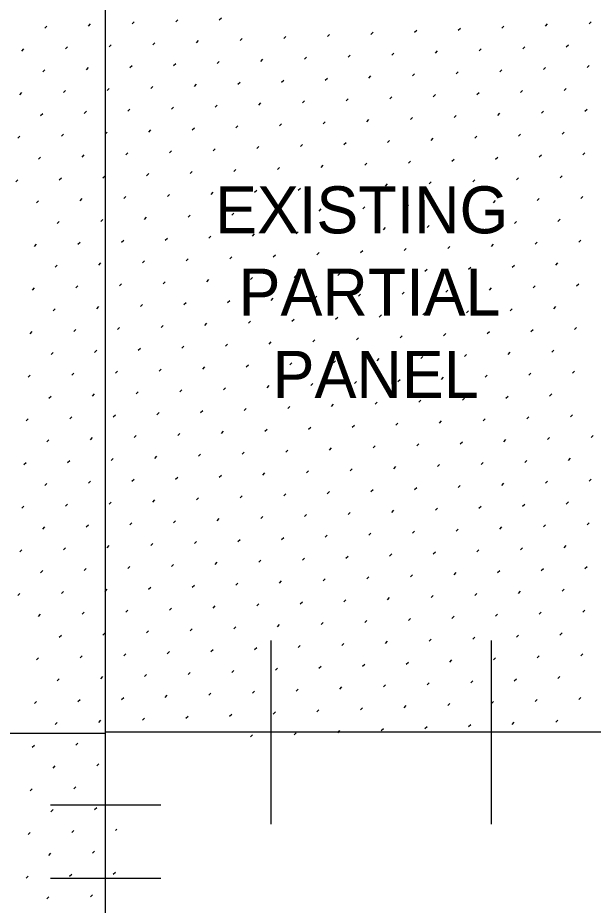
# Model space of a CAD drawing. Extents: x 49991.4 to 50021, y 49987.6 to 50011.4.
# Drawn here: x 50009.66 to 50010.64, y 49995.997 to 49997.507 of the extents above; entities that cross this region are included whole.
import ezdxf

# ---------------------------------------------------------------- set-up
doc = ezdxf.new("R2010")
doc.units = 0
for name, color, linetype in [('Level 1', 7, 'Continuous'), ('Level 10', 7, 'Continuous'), ('Level 2', 7, 'Continuous'), ('Level 4', 7, 'Continuous')]:
    doc.layers.add(name, color=color, linetype=linetype)

msp = doc.modelspace()

# ---------------------------------------------------------------- linework, layer by layer
at = {"layer": 'Level 1'}
for p, q in [((50009.8098, 49996.2901), (50009.8098, 49997.7903)), ((50008.8723, 49996.2901), (50009.8098, 49996.2901)), ((50011.6848, 49996.2915), (50009.8098, 49996.2915)), ((50009.8098, 49994.7903), (50009.8098, 49996.2901))]:
    msp.add_line(p, q, dxfattribs=at)
at = {"layer": 'Level 10'}
for p, q in [((50009.8548, 49997.4965), (50009.8584, 49997.5)), ((50009.9291, 49997.5), (50009.9326, 49997.5036)), ((50010.0033, 49997.5036), (50010.0069, 49997.5071)), ((50010.6327, 49997.4966), (50010.6362, 49997.5001)), ((50009.7063, 49997.4894), (50009.7098, 49997.4929)), ((50009.7806, 49997.4929), (50009.7841, 49997.4965)), ((50010.2614, 49997.4788), (50010.265, 49997.4824)), ((50010.3357, 49997.4824), (50010.3392, 49997.4859)), ((50010.4099, 49997.4859), (50010.4135, 49997.4895)), ((50010.4842, 49997.4895), (50010.4877, 49997.493)), ((50010.5585, 49997.493), (50010.562, 49997.4965)), ((50009.9644, 49997.4647), (50009.968, 49997.4682)), ((50010.0387, 49997.4682), (50010.0422, 49997.4717)), ((50010.1129, 49997.4718), (50010.1165, 49997.4753)), ((50010.1872, 49997.4753), (50010.1907, 49997.4788)), ((50009.6674, 49997.4505), (50009.6709, 49997.454)), ((50009.7417, 49997.454), (50009.7452, 49997.4576)), ((50009.8159, 49997.4576), (50009.8195, 49997.4611)), ((50009.8902, 49997.4611), (50009.8937, 49997.4647)), ((50010.4453, 49997.4506), (50010.4488, 49997.4541)), ((50010.5196, 49997.4541), (50010.5231, 49997.4576)), ((50010.5938, 49997.4577), (50010.5973, 49997.4612)), ((50010.1483, 49997.4364), (50010.1518, 49997.4399)), ((50010.2225, 49997.4399), (50010.2261, 49997.4435)), ((50010.2968, 49997.4435), (50010.3003, 49997.447)), ((50010.371, 49997.447), (50010.3746, 49997.4506)), ((50009.777, 49997.4187), (50009.7806, 49997.4222)), ((50009.8513, 49997.4222), (50009.8548, 49997.4258)), ((50009.9255, 49997.4258), (50009.9291, 49997.4293)), ((50009.9998, 49997.4293), (50010.0033, 49997.4328)), ((50010.074, 49997.4329), (50010.0776, 49997.4364)), ((50010.5549, 49997.4188), (50010.5584, 49997.4223)), ((50010.6292, 49997.4223), (50010.6327, 49997.4258)), ((50009.7028, 49997.4151), (50009.7063, 49997.4187)), ((50010.2579, 49997.4046), (50010.2614, 49997.4081)), ((50010.3321, 49997.4081), (50010.3357, 49997.4117)), ((50010.4064, 49997.4117), (50010.4099, 49997.4152)), ((50010.4807, 49997.4152), (50010.4842, 49997.4187)), ((50009.9609, 49997.3904), (50009.9644, 49997.394)), ((50010.0351, 49997.394), (50010.0387, 49997.3975)), ((50010.1094, 49997.3975), (50010.1129, 49997.401)), ((50010.1836, 49997.401), (50010.1872, 49997.4046)), ((50009.6639, 49997.3762), (50009.6674, 49997.3798)), ((50009.7381, 49997.3798), (50009.7417, 49997.3833)), ((50009.8124, 49997.3833), (50009.8159, 49997.3869)), ((50009.8866, 49997.3869), (50009.8902, 49997.3904)), ((50010.4418, 49997.3763), (50010.4453, 49997.3799)), ((50010.516, 49997.3799), (50010.5195, 49997.3834)), ((50010.5903, 49997.3834), (50010.5938, 49997.3869)), ((50010.0705, 49997.3586), (50010.074, 49997.3621)), ((50010.1447, 49997.3621), (50010.1483, 49997.3657)), ((50010.219, 49997.3657), (50010.2225, 49997.3692)), ((50010.2933, 49997.3692), (50010.2968, 49997.3728)), ((50010.3675, 49997.3728), (50010.371, 49997.3763)), ((50009.7735, 49997.3444), (50009.777, 49997.348)), ((50009.8477, 49997.348), (50009.8513, 49997.3515)), ((50009.922, 49997.3515), (50009.9255, 49997.3551)), ((50009.9962, 49997.3551), (50009.9998, 49997.3586)), ((50010.5514, 49997.3445), (50010.5549, 49997.348)), ((50010.6256, 49997.348), (50010.6292, 49997.3516)), ((50009.6992, 49997.3409), (50009.7028, 49997.3444)), ((50010.2544, 49997.3303), (50010.2579, 49997.3339)), ((50010.3286, 49997.3339), (50010.3321, 49997.3374)), ((50010.4029, 49997.3374), (50010.4064, 49997.341)), ((50010.4771, 49997.341), (50010.4806, 49997.3445)), ((50009.8831, 49997.3126), (50009.8866, 49997.3162)), ((50009.9573, 49997.3162), (50009.9609, 49997.3197)), ((50010.0316, 49997.3197), (50010.0351, 49997.3232)), ((50010.1058, 49997.3232), (50010.1094, 49997.3268)), ((50010.1801, 49997.3268), (50010.1836, 49997.3303)), ((50009.6603, 49997.302), (50009.6639, 49997.3055)), ((50009.7346, 49997.3055), (50009.7381, 49997.3091)), ((50009.8088, 49997.3091), (50009.8124, 49997.3126)), ((50010.364, 49997.2985), (50010.3675, 49997.3021)), ((50010.4382, 49997.3021), (50010.4417, 49997.3056)), ((50010.5125, 49997.3056), (50010.516, 49997.3091)), ((50010.5867, 49997.3091), (50010.5903, 49997.3127)), ((50010.0669, 49997.2844), (50010.0705, 49997.2879)), ((50010.1412, 49997.2879), (50010.1447, 49997.2914)), ((50010.2155, 49997.2914), (50010.219, 49997.295)), ((50010.2897, 49997.295), (50010.2932, 49997.2985)), ((50009.7699, 49997.2702), (50009.7735, 49997.2737)), ((50009.8442, 49997.2737), (50009.8477, 49997.2773)), ((50009.9184, 49997.2773), (50009.922, 49997.2808)), ((50009.9927, 49997.2808), (50009.9962, 49997.2843)), ((50010.5478, 49997.2703), (50010.5514, 49997.2738)), ((50010.6221, 49997.2738), (50010.6256, 49997.2773)), ((50009.6957, 49997.2666), (50009.6992, 49997.2702)), ((50010.1766, 49997.2525), (50010.1801, 49997.2561)), ((50010.2508, 49997.2561), (50010.2543, 49997.2596)), ((50010.3251, 49997.2596), (50010.3286, 49997.2632)), ((50010.3993, 49997.2632), (50010.4029, 49997.2667)), ((50010.4736, 49997.2667), (50010.4771, 49997.2702)), ((50009.8795, 49997.2384), (50009.8831, 49997.2419)), ((50009.9538, 49997.2419), (50009.9573, 49997.2454)), ((50010.0281, 49997.2455), (50010.0316, 49997.249)), ((50010.1023, 49997.249), (50010.1058, 49997.2525)), ((50009.6568, 49997.2277), (50009.6603, 49997.2313)), ((50009.731, 49997.2313), (50009.7346, 49997.2348)), ((50009.8053, 49997.2348), (50009.8088, 49997.2384)), ((50010.3604, 49997.2243), (50010.364, 49997.2278)), ((50010.4347, 49997.2278), (50010.4382, 49997.2313)), ((50010.5089, 49997.2314), (50010.5125, 49997.2349)), ((50010.5832, 49997.2349), (50010.5867, 49997.2384)), ((50010.0634, 49997.2101), (50010.0669, 49997.2136)), ((50010.1377, 49997.2136), (50010.1412, 49997.2172)), ((50010.2119, 49997.2172), (50010.2154, 49997.2207)), ((50010.2862, 49997.2207), (50010.2897, 49997.2243)), ((50009.6921, 49997.1924), (50009.6957, 49997.1959)), ((50009.7664, 49997.1959), (50009.7699, 49997.1995)), ((50009.8406, 49997.1995), (50009.8442, 49997.203)), ((50009.9149, 49997.203), (50009.9184, 49997.2065)), ((50009.9892, 49997.2066), (50009.9927, 49997.2101)), ((50010.47, 49997.1925), (50010.4736, 49997.196)), ((50010.5443, 49997.196), (50010.5478, 49997.1995)), ((50010.6185, 49997.1995), (50010.6221, 49997.2031)), ((50010.173, 49997.1783), (50010.1765, 49997.1818)), ((50010.2473, 49997.1818), (50010.2508, 49997.1854)), ((50010.3215, 49997.1854), (50010.3251, 49997.1889)), ((50010.3958, 49997.1889), (50010.3993, 49997.1924)), ((50009.876, 49997.1641), (50009.8795, 49997.1676)), ((50009.9503, 49997.1677), (50009.9538, 49997.1712)), ((50010.0245, 49997.1712), (50010.028, 49997.1747)), ((50010.0988, 49997.1747), (50010.1023, 49997.1783)), ((50009.7275, 49997.157), (50009.731, 49997.1606)), ((50009.8017, 49997.1606), (50009.8053, 49997.1641)), ((50010.2826, 49997.1465), (50010.2862, 49997.15)), ((50010.3569, 49997.15), (50010.3604, 49997.1535)), ((50010.4311, 49997.1536), (50010.4347, 49997.1571)), ((50010.5054, 49997.1571), (50010.5089, 49997.1606)), ((50010.5796, 49997.1606), (50010.5832, 49997.1642)), ((50009.9856, 49997.1323), (50009.9891, 49997.1358)), ((50010.0599, 49997.1358), (50010.0634, 49997.1394)), ((50010.1341, 49997.1394), (50010.1377, 49997.1429)), ((50010.2084, 49997.1429), (50010.2119, 49997.1465)), ((50009.6886, 49997.1181), (50009.6921, 49997.1217)), ((50009.7628, 49997.1217), (50009.7664, 49997.1252)), ((50009.8371, 49997.1252), (50009.8406, 49997.1288)), ((50009.9114, 49997.1288), (50009.9149, 49997.1323)), ((50010.4665, 49997.1182), (50010.47, 49997.1217)), ((50010.5407, 49997.1217), (50010.5443, 49997.1253)), ((50010.615, 49997.1253), (50010.6185, 49997.1288)), ((50010.1695, 49997.104), (50010.173, 49997.1076)), ((50010.2437, 49997.1076), (50010.2473, 49997.1111)), ((50010.318, 49997.1111), (50010.3215, 49997.1147)), ((50010.3922, 49997.1147), (50010.3958, 49997.1182)), ((50009.7982, 49997.0863), (50009.8017, 49997.0899)), ((50009.8725, 49997.0899), (50009.876, 49997.0934)), ((50009.9467, 49997.0934), (50009.9502, 49997.0969)), ((50010.021, 49997.0969), (50010.0245, 49997.1005)), ((50010.0952, 49997.1005), (50010.0988, 49997.104)), ((50010.5761, 49997.0864), (50010.5796, 49997.0899)), ((50009.724, 49997.0828), (50009.7275, 49997.0863)), ((50010.2791, 49997.0722), (50010.2826, 49997.0758)), ((50010.3533, 49997.0758), (50010.3569, 49997.0793)), ((50010.4276, 49997.0793), (50010.4311, 49997.0828)), ((50010.5018, 49997.0828), (50010.5054, 49997.0864)), ((50009.9821, 49997.058), (50009.9856, 49997.0616)), ((50010.0563, 49997.0616), (50010.0599, 49997.0651)), ((50010.1306, 49997.0651), (50010.1341, 49997.0687)), ((50010.2048, 49997.0687), (50010.2084, 49997.0722)), ((50009.6851, 49997.0439), (50009.6886, 49997.0474)), ((50009.7593, 49997.0474), (50009.7628, 49997.051)), ((50009.8336, 49997.051), (50009.8371, 49997.0545)), ((50009.9078, 49997.0545), (50009.9113, 49997.058)), ((50010.4629, 49997.0439), (50010.4665, 49997.0475)), ((50010.5372, 49997.0475), (50010.5407, 49997.051)), ((50010.6114, 49997.051), (50010.615, 49997.0546)), ((50010.0917, 49997.0262), (50010.0952, 49997.0298)), ((50010.1659, 49997.0298), (50010.1695, 49997.0333)), ((50010.2402, 49997.0333), (50010.2437, 49997.0369)), ((50010.3144, 49997.0369), (50010.318, 49997.0404)), ((50010.3887, 49997.0404), (50010.3922, 49997.0439)), ((50009.7947, 49997.0121), (50009.7982, 49997.0156)), ((50009.8689, 49997.0156), (50009.8725, 49997.0191)), ((50009.9432, 49997.0191), (50009.9467, 49997.0227)), ((50010.0174, 49997.0227), (50010.021, 49997.0262)), ((50010.5726, 49997.0121), (50010.5761, 49997.0157)), ((50009.7204, 49997.0085), (50009.7239, 49997.0121)), ((50010.2755, 49996.998), (50010.2791, 49997.0015)), ((50010.3498, 49997.0015), (50010.3533, 49997.005)), ((50010.424, 49997.005), (50010.4276, 49997.0086)), ((50010.4983, 49997.0086), (50010.5018, 49997.0121)), ((50009.9785, 49996.9838), (50009.9821, 49996.9873)), ((50010.0528, 49996.9873), (50010.0563, 49996.9909)), ((50010.127, 49996.9909), (50010.1306, 49996.9944)), ((50010.2013, 49996.9944), (50010.2048, 49996.998)), ((50009.6815, 49996.9696), (50009.685, 49996.9732)), ((50009.7558, 49996.9732), (50009.7593, 49996.9767)), ((50009.83, 49996.9767), (50009.8336, 49996.9802)), ((50009.9043, 49996.9803), (50009.9078, 49996.9838)), ((50010.3851, 49996.9662), (50010.3887, 49996.9697)), ((50010.4594, 49996.9697), (50010.4629, 49996.9732)), ((50010.5337, 49996.9732), (50010.5372, 49996.9768)), ((50010.6079, 49996.9768), (50010.6114, 49996.9803)), ((50010.0881, 49996.952), (50010.0917, 49996.9555)), ((50010.1624, 49996.9555), (50010.1659, 49996.9591)), ((50010.2366, 49996.9591), (50010.2402, 49996.9626)), ((50010.3109, 49996.9626), (50010.3144, 49996.9661)), ((50009.7911, 49996.9378), (50009.7947, 49996.9413)), ((50009.8654, 49996.9414), (50009.8689, 49996.9449)), ((50009.9396, 49996.9449), (50009.9432, 49996.9484)), ((50010.0139, 49996.9484), (50010.0174, 49996.952)), ((50010.569, 49996.9379), (50010.5725, 49996.9414)), ((50009.7169, 49996.9343), (50009.7204, 49996.9378)), ((50010.1977, 49996.9202), (50010.2013, 49996.9237)), ((50010.272, 49996.9237), (50010.2755, 49996.9272)), ((50010.3462, 49996.9273), (50010.3498, 49996.9308)), ((50010.4205, 49996.9308), (50010.424, 49996.9343)), ((50010.4948, 49996.9343), (50010.4983, 49996.9379)), ((50009.9007, 49996.906), (50009.9043, 49996.9095)), ((50009.975, 49996.9095), (50009.9785, 49996.9131)), ((50010.0492, 49996.9131), (50010.0528, 49996.9166)), ((50010.1235, 49996.9166), (50010.127, 49996.9202)), ((50009.678, 49996.8954), (50009.6815, 49996.8989)), ((50009.7522, 49996.8989), (50009.7558, 49996.9024)), ((50009.8265, 49996.9025), (50009.83, 49996.906)), ((50010.3816, 49996.8919), (50010.3851, 49996.8954)), ((50010.4559, 49996.8954), (50010.4594, 49996.899)), ((50010.5301, 49996.899), (50010.5336, 49996.9025)), ((50010.6044, 49996.9025), (50010.6079, 49996.9061)), ((50010.0846, 49996.8777), (50010.0881, 49996.8813)), ((50010.1588, 49996.8813), (50010.1624, 49996.8848)), ((50010.2331, 49996.8848), (50010.2366, 49996.8883)), ((50010.3074, 49996.8884), (50010.3109, 49996.8919)), ((50009.7133, 49996.86), (50009.7169, 49996.8636)), ((50009.7876, 49996.8636), (50009.7911, 49996.8671)), ((50009.8618, 49996.8671), (50009.8654, 49996.8706)), ((50009.9361, 49996.8706), (50009.9396, 49996.8742)), ((50010.0103, 49996.8742), (50010.0139, 49996.8777)), ((50010.4912, 49996.8601), (50010.4947, 49996.8636)), ((50010.5655, 49996.8636), (50010.569, 49996.8672)), ((50010.1942, 49996.8459), (50010.1977, 49996.8495)), ((50010.2685, 49996.8495), (50010.272, 49996.853)), ((50010.3427, 49996.853), (50010.3462, 49996.8565)), ((50010.417, 49996.8565), (50010.4205, 49996.8601)), ((50009.8972, 49996.8317), (50009.9007, 49996.8353)), ((50009.9714, 49996.8353), (50009.975, 49996.8388)), ((50010.0457, 49996.8388), (50010.0492, 49996.8424)), ((50010.1199, 49996.8424), (50010.1235, 49996.8459)), ((50009.6744, 49996.8211), (50009.678, 49996.8247)), ((50009.7487, 49996.8247), (50009.7522, 49996.8282)), ((50009.8229, 49996.8282), (50009.8265, 49996.8317)), ((50010.3781, 49996.8176), (50010.3816, 49996.8212)), ((50010.4523, 49996.8212), (50010.4558, 49996.8247)), ((50010.5266, 49996.8247), (50010.5301, 49996.8283)), ((50010.6008, 49996.8283), (50010.6044, 49996.8318)), ((50010.0068, 49996.7999), (50010.0103, 49996.8035)), ((50010.081, 49996.8035), (50010.0846, 49996.807)), ((50010.1553, 49996.807), (50010.1588, 49996.8106)), ((50010.2296, 49996.8106), (50010.2331, 49996.8141)), ((50010.3038, 49996.8141), (50010.3073, 49996.8176)), ((50009.7098, 49996.7858), (50009.7133, 49996.7893)), ((50009.784, 49996.7893), (50009.7876, 49996.7928)), ((50009.8583, 49996.7928), (50009.8618, 49996.7964)), ((50009.9325, 49996.7964), (50009.9361, 49996.7999)), ((50010.4877, 49996.7858), (50010.4912, 49996.7894)), ((50010.5619, 49996.7894), (50010.5655, 49996.7929)), ((50010.6362, 49996.7929), (50010.6397, 49996.7965)), ((50010.1907, 49996.7717), (50010.1942, 49996.7752)), ((50010.2649, 49996.7752), (50010.2684, 49996.7787)), ((50010.3392, 49996.7787), (50010.3427, 49996.7823)), ((50010.4134, 49996.7823), (50010.417, 49996.7858)), ((50009.8194, 49996.7539), (50009.8229, 49996.7575)), ((50009.8936, 49996.7575), (50009.8972, 49996.761)), ((50009.9679, 49996.761), (50009.9714, 49996.7646)), ((50010.0421, 49996.7646), (50010.0457, 49996.7681)), ((50010.1164, 49996.7681), (50010.1199, 49996.7717)), ((50010.5973, 49996.754), (50010.6008, 49996.7576)), ((50009.6709, 49996.7469), (50009.6744, 49996.7504)), ((50009.7451, 49996.7504), (50009.7487, 49996.7539)), ((50010.3003, 49996.7398), (50010.3038, 49996.7434)), ((50010.3745, 49996.7434), (50010.3781, 49996.7469)), ((50010.4488, 49996.7469), (50010.4523, 49996.7505)), ((50010.523, 49996.7505), (50010.5266, 49996.754)), ((50010.0033, 49996.7257), (50010.0068, 49996.7292)), ((50010.0775, 49996.7292), (50010.081, 49996.7328)), ((50010.1518, 49996.7328), (50010.1553, 49996.7363)), ((50010.226, 49996.7363), (50010.2295, 49996.7398)), ((50009.7062, 49996.7115), (50009.7098, 49996.715)), ((50009.7805, 49996.7151), (50009.784, 49996.7186)), ((50009.8547, 49996.7186), (50009.8583, 49996.7221)), ((50009.929, 49996.7221), (50009.9325, 49996.7257)), ((50010.4841, 49996.7116), (50010.4877, 49996.7151)), ((50010.5584, 49996.7151), (50010.5619, 49996.7187)), ((50010.6326, 49996.7187), (50010.6362, 49996.7222)), ((50010.1129, 49996.6939), (50010.1164, 49996.6974)), ((50010.1871, 49996.6974), (50010.1906, 49996.7009)), ((50010.2614, 49996.701), (50010.2649, 49996.7045)), ((50010.3356, 49996.7045), (50010.3392, 49996.708)), ((50010.4099, 49996.708), (50010.4134, 49996.7116)), ((50009.8158, 49996.6797), (50009.8194, 49996.6832)), ((50009.8901, 49996.6832), (50009.8936, 49996.6868)), ((50009.9644, 49996.6868), (50009.9679, 49996.6903)), ((50010.0386, 49996.6903), (50010.0421, 49996.6939)), ((50010.5937, 49996.6798), (50010.5973, 49996.6833)), ((50009.6673, 49996.6726), (50009.6709, 49996.6761)), ((50009.7416, 49996.6762), (50009.7451, 49996.6797)), ((50010.2967, 49996.6656), (50010.3003, 49996.6691)), ((50010.371, 49996.6691), (50010.3745, 49996.6727)), ((50010.4452, 49996.6727), (50010.4488, 49996.6762)), ((50010.5195, 49996.6762), (50010.523, 49996.6798)), ((50009.9997, 49996.6514), (50010.0032, 49996.655)), ((50010.074, 49996.655), (50010.0775, 49996.6585)), ((50010.1482, 49996.6585), (50010.1518, 49996.662)), ((50010.2225, 49996.6621), (50010.226, 49996.6656)), ((50009.7027, 49996.6373), (50009.7062, 49996.6408)), ((50009.7769, 49996.6408), (50009.7805, 49996.6443)), ((50009.8512, 49996.6443), (50009.8547, 49996.6479)), ((50009.9255, 49996.6479), (50009.929, 49996.6514)), ((50010.4063, 49996.6338), (50010.4099, 49996.6373)), ((50010.4806, 49996.6373), (50010.4841, 49996.6409)), ((50010.5548, 49996.6409), (50010.5584, 49996.6444)), ((50010.6291, 49996.6444), (50010.6326, 49996.6479)), ((50010.1093, 49996.6196), (50010.1129, 49996.6231)), ((50010.1836, 49996.6232), (50010.1871, 49996.6267)), ((50010.2578, 49996.6267), (50010.2614, 49996.6302)), ((50010.3321, 49996.6302), (50010.3356, 49996.6338)), ((50009.8123, 49996.6054), (50009.8158, 49996.609)), ((50009.8866, 49996.609), (50009.8901, 49996.6125)), ((50009.9608, 49996.6125), (50009.9643, 49996.6161)), ((50010.0351, 49996.6161), (50010.0386, 49996.6196)), ((50010.5902, 49996.6055), (50010.5937, 49996.609)), ((50009.6638, 49996.5984), (50009.6673, 49996.6019)), ((50009.7381, 49996.6019), (50009.7416, 49996.6054)), ((50010.2189, 49996.5878), (50010.2225, 49996.5913)), ((50010.2932, 49996.5913), (50010.2967, 49996.5949)), ((50010.3674, 49996.5949), (50010.371, 49996.5984)), ((50010.4417, 49996.5984), (50010.4452, 49996.602)), ((50010.5159, 49996.602), (50010.5195, 49996.6055)), ((50009.9219, 49996.5736), (50009.9254, 49996.5772)), ((50009.9962, 49996.5772), (50009.9997, 49996.5807)), ((50010.0704, 49996.5807), (50010.074, 49996.5843)), ((50010.1447, 49996.5843), (50010.1482, 49996.5878)), ((50009.6992, 49996.563), (50009.7027, 49996.5665)), ((50009.7734, 49996.5665), (50009.7769, 49996.5701)), ((50009.8477, 49996.5701), (50009.8512, 49996.5736)), ((50010.4028, 49996.5595), (50010.4063, 49996.5631)), ((50010.477, 49996.5631), (50010.4806, 49996.5666)), ((50010.5513, 49996.5666), (50010.5548, 49996.5702)), ((50010.6255, 49996.5702), (50010.6291, 49996.5737)), ((50010.1058, 49996.5454), (50010.1093, 49996.5489)), ((50010.18, 49996.5489), (50010.1836, 49996.5524)), ((50010.2543, 49996.5524), (50010.2578, 49996.556)), ((50010.3285, 49996.556), (50010.3321, 49996.5595)), ((50009.7345, 49996.5276), (50009.738, 49996.5312)), ((50009.8088, 49996.5312), (50009.8123, 49996.5347)), ((50009.883, 49996.5347), (50009.8866, 49996.5383)), ((50009.9573, 49996.5383), (50009.9608, 49996.5418)), ((50010.0315, 49996.5418), (50010.0351, 49996.5454)), ((50010.5124, 49996.5277), (50010.5159, 49996.5313)), ((50010.5867, 49996.5313), (50010.5902, 49996.5348)), ((50009.6603, 49996.5241), (50009.6638, 49996.5276)), ((50010.2154, 49996.5135), (50010.2189, 49996.5171)), ((50010.2896, 49996.5171), (50010.2932, 49996.5206)), ((50010.3639, 49996.5206), (50010.3674, 49996.5242)), ((50010.4381, 49996.5242), (50010.4417, 49996.5277)), ((50009.9184, 49996.4994), (50009.9219, 49996.5029)), ((50009.9926, 49996.5029), (50009.9962, 49996.5065)), ((50010.0669, 49996.5065), (50010.0704, 49996.51)), ((50010.1411, 49996.51), (50010.1447, 49996.5135)), ((50009.6956, 49996.4887), (50009.6991, 49996.4923)), ((50009.7699, 49996.4923), (50009.7734, 49996.4958)), ((50009.8441, 49996.4958), (50009.8477, 49996.4994)), ((50010.3992, 49996.4853), (50010.4028, 49996.4888)), ((50010.4735, 49996.4888), (50010.477, 49996.4924)), ((50010.5478, 49996.4924), (50010.5513, 49996.4959)), ((50010.622, 49996.4959), (50010.6255, 49996.4994)), ((50010.028, 49996.4676), (50010.0315, 49996.4711)), ((50010.1022, 49996.4711), (50010.1058, 49996.4746)), ((50010.1765, 49996.4746), (50010.18, 49996.4782)), ((50010.2507, 49996.4782), (50010.2543, 49996.4817)), ((50010.325, 49996.4817), (50010.3285, 49996.4853)), ((50009.731, 49996.4534), (50009.7345, 49996.4569)), ((50009.8052, 49996.4569), (50009.8088, 49996.4605)), ((50009.8795, 49996.4605), (50009.883, 49996.464)), ((50009.9537, 49996.464), (50009.9573, 49996.4676)), ((50010.5089, 49996.4535), (50010.5124, 49996.457)), ((50010.5831, 49996.457), (50010.5866, 49996.4605)), ((50010.2118, 49996.4393), (50010.2154, 49996.4428)), ((50010.2861, 49996.4428), (50010.2896, 49996.4464)), ((50010.3603, 49996.4464), (50010.3639, 49996.4499)), ((50010.4346, 49996.4499), (50010.4381, 49996.4535)), ((50009.9148, 49996.4251), (50009.9184, 49996.4287)), ((50009.9891, 49996.4287), (50009.9926, 49996.4322)), ((50010.0633, 49996.4322), (50010.0669, 49996.4357)), ((50010.1376, 49996.4358), (50010.1411, 49996.4393)), ((50010.6185, 49996.4217), (50010.622, 49996.4252)), ((50009.6921, 49996.4145), (50009.6956, 49996.418)), ((50009.7663, 49996.418), (50009.7699, 49996.4216)), ((50009.8406, 49996.4216), (50009.8441, 49996.4251)), ((50010.3214, 49996.4075), (50010.325, 49996.411)), ((50010.3957, 49996.411), (50010.3992, 49996.4146)), ((50010.47, 49996.4146), (50010.4735, 49996.4181)), ((50010.5442, 49996.4181), (50010.5477, 49996.4216)), ((50010.0244, 49996.3933), (50010.028, 49996.3968)), ((50010.0987, 49996.3969), (50010.1022, 49996.4004)), ((50010.1729, 49996.4004), (50010.1765, 49996.4039)), ((50010.2472, 49996.4039), (50010.2507, 49996.4075)), ((50009.7274, 49996.3791), (50009.731, 49996.3827)), ((50009.8017, 49996.3827), (50009.8052, 49996.3862)), ((50009.8759, 49996.3862), (50009.8795, 49996.3898)), ((50009.9502, 49996.3898), (50009.9537, 49996.3933)), ((50010.5053, 49996.3792), (50010.5088, 49996.3827)), ((50010.5796, 49996.3828), (50010.5831, 49996.3863)), ((50010.134, 49996.3615), (50010.1376, 49996.365)), ((50010.2083, 49996.365), (50010.2118, 49996.3686)), ((50010.2826, 49996.3686), (50010.2861, 49996.3721)), ((50010.3568, 49996.3721), (50010.3603, 49996.3757)), ((50010.4311, 49996.3757), (50010.4346, 49996.3792)), ((50009.837, 49996.3473), (50009.8406, 49996.3509)), ((50009.9113, 49996.3509), (50009.9148, 49996.3544)), ((50009.9855, 49996.3544), (50009.9891, 49996.3579)), ((50010.0598, 49996.358), (50010.0633, 49996.3615)), ((50010.6149, 49996.3474), (50010.6185, 49996.3509)), ((50009.6885, 49996.3402), (50009.6921, 49996.3438)), ((50009.7628, 49996.3438), (50009.7663, 49996.3473)), ((50010.3179, 49996.3332), (50010.3214, 49996.3368)), ((50010.3922, 49996.3368), (50010.3957, 49996.3403)), ((50010.4664, 49996.3403), (50010.4699, 49996.3438)), ((50010.5407, 49996.3439), (50010.5442, 49996.3474)), ((50010.0209, 49996.3191), (50010.0244, 49996.3226)), ((50010.0951, 49996.3226), (50010.0987, 49996.3261)), ((50010.1694, 49996.3261), (50010.1729, 49996.3297)), ((50010.2437, 49996.3297), (50010.2472, 49996.3332)), ((50009.7239, 49996.3049), (50009.7274, 49996.3084)), ((50009.7981, 49996.3084), (50009.8017, 49996.312)), ((50009.8724, 49996.312), (50009.8759, 49996.3155)), ((50009.9466, 49996.3155), (50009.9502, 49996.3191)), ((50010.4275, 49996.3014), (50010.4311, 49996.305)), ((50010.5018, 49996.305), (50010.5053, 49996.3085)), ((50010.576, 49996.3085), (50010.5796, 49996.312)), ((50010.1305, 49996.2872), (50010.134, 49996.2908)), ((50010.2048, 49996.2908), (50010.2083, 49996.2943)), ((50010.279, 49996.2943), (50010.2825, 49996.2979)), ((50010.3533, 49996.2979), (50010.3568, 49996.3014)), ((50010.0564, 49996.2838), (50010.0598, 49996.2872)), ((50009.685, 49996.266), (50009.6885, 49996.2695)), ((50009.7592, 49996.2695), (50009.7628, 49996.2731)), ((50009.7203, 49996.2306), (50009.7239, 49996.2342)), ((50009.7946, 49996.2342), (50009.7981, 49996.2377)), ((50009.7557, 49996.1953), (50009.7592, 49996.1988)), ((50009.6814, 49996.1917), (50009.685, 49996.1953)), ((50009.7168, 49996.1564), (50009.7203, 49996.1599)), ((50009.791, 49996.1599), (50009.7946, 49996.1635)), ((50009.7522, 49996.121), (50009.7557, 49996.1246)), ((50009.8264, 49996.1246), (50009.8288, 49996.1269)), ((50009.6779, 49996.1175), (50009.6814, 49996.121)), ((50009.7133, 49996.0821), (50009.7168, 49996.0857)), ((50009.7875, 49996.0857), (50009.791, 49996.0892)), ((50009.7486, 49996.0468), (50009.7521, 49996.0503)), ((50009.8229, 49996.0503), (50009.8264, 49996.0538)), ((50009.6744, 49996.0432), (50009.6779, 49996.0468)), ((50009.7097, 49996.0079), (50009.7132, 49996.0114)), ((50009.784, 49996.0114), (50009.7875, 49996.015))]:
    msp.add_line(p, q, dxfattribs=at)
at = {"layer": 'Level 4'}
for p, q in [((50010.091, 49996.4478), (50010.091, 49996.1353)), ((50010.466, 49996.4478), (50010.466, 49996.1353)), ((50009.9035, 49996.1677), (50009.716, 49996.1677)), ((50009.9035, 49996.0427), (50009.716, 49996.0427))]:
    msp.add_line(p, q, dxfattribs=at)

# ---------------------------------------------------------------- texts
at = {"layer": 'Level 2'}
for s, p in [('EXISTING', (50009.9961, 49997.1403)), ('PARTIAL', (50010.0361, 49997.0003)), ('PANEL', (50010.094, 49996.8603))]:
    msp.add_text(s, height=0.08, dxfattribs=at).set_placement(p)

doc.saveas('drawing.dxf')
